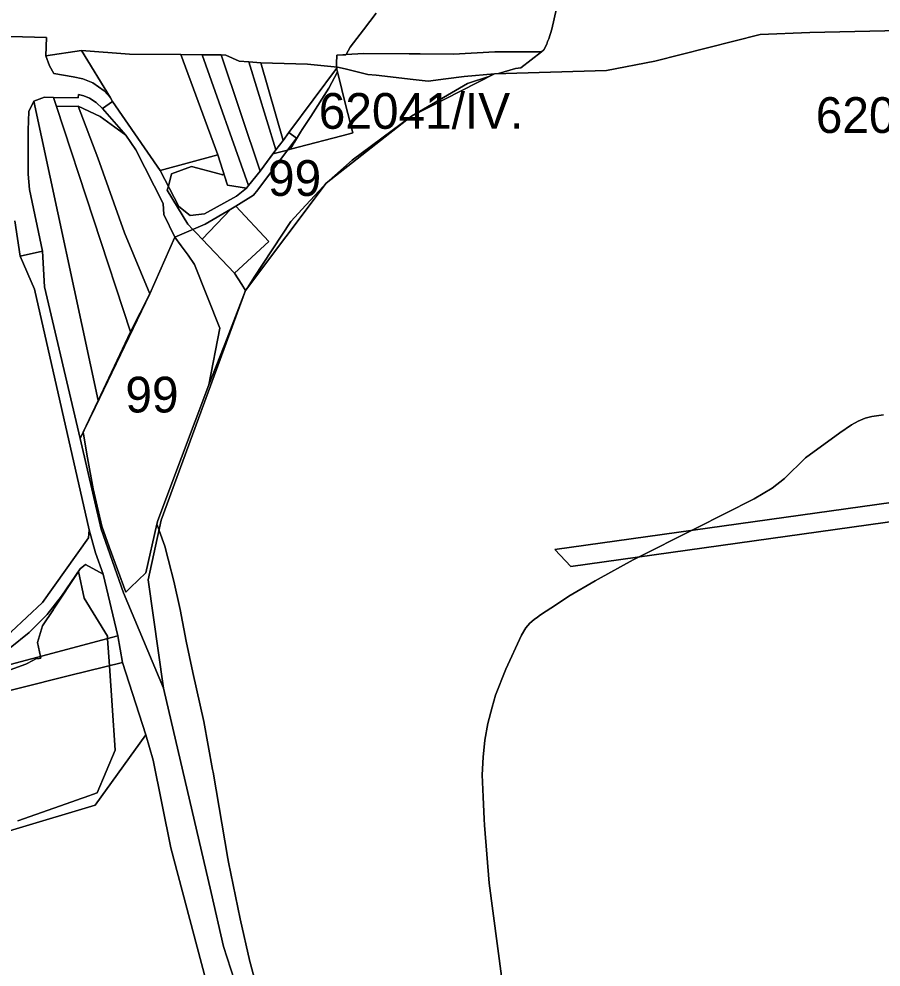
# Model space of a CAD drawing. Extents: x -521939 to -516426, y -1197857 to -1189551.
# Drawn here: x -519093.3 to -518731.6, y -1193402.1 to -1193004.4 of the extents above; entities that cross this region are included whole.
import ezdxf

# ---------------------------------------------------------------- set-up
doc = ezdxf.new("R2010")
doc.units = 0
for name, color, linetype in [('95560013', 7, 'Continuous'), ('95600013', 7, 'Continuous'), ('95610013', 7, 'Continuous'), ('95620013', 7, 'Continuous'), ('95640013', 7, 'Continuous'), ('95660013', 7, 'Continuous')]:
    doc.layers.add(name, color=color, linetype=linetype)

msp = doc.modelspace()

# ---------------------------------------------------------------- linework, layer by layer
at = {"layer": '95560013'}
msp.add_lwpolyline([(-519009.88, -1193061.29), (-519025.46, -1193019.32), (-519016.37, -1193019.41), (-518997.03, -1193074.16), (-518997.79, -1193075.34), (-519005.77, -1193074.1)], close=True, dxfattribs=at)
at = {"layer": '95600013'}
for points in [[(-519001.34, -1193412.48), (-519007.46, -1193393.47), (-519012.64, -1193370.77), (-519032.72, -1193285.1), (-519039.05, -1193239.66), (-519033.58, -1193214.67), (-518998.24, -1193118.29), (-518964.46, -1193073.28), (-518928.64, -1193045.14), (-518893.72, -1193027.32), (-518846.7, -1193025.98), (-518826.54, -1193022.13), (-518782.28, -1193010.93), (-518761.5, -1193009.97), (-518654.27, -1193007.7)], [(-518688.29, -1193201.76), (-518868.39, -1193226.97), (-518861.71, -1193234.11), (-518680.88, -1193208.8)]]:
    msp.add_lwpolyline(points, dxfattribs=at)
at = {"layer": '95610013'}
for points in [[(-519054.97, -1193037.51), (-519067.01, -1193017.55), (-519046.96, -1193019.18), (-519025.46, -1193019.32), (-519009.88, -1193061.29), (-519034.04, -1193067.86), (-519054.02, -1193039.03)], [(-518997.03, -1193074.16), (-519016.37, -1193019.41), (-519008.43, -1193019.45), (-518992.15, -1193068.17)], [(-518992.15, -1193068.17), (-519008.43, -1193019.45), (-519006.51, -1193019.53), (-519000.94, -1193022.11), (-518996.85, -1193022.41), (-518985.57, -1193059.25)], [(-518982.48, -1193055.34), (-518985.57, -1193059.25), (-518996.85, -1193022.41), (-518991.81, -1193022.8)], [(-518982.48, -1193055.34), (-518991.81, -1193022.8), (-518972.24, -1193023.25), (-518959.64, -1193024.58), (-518980, -1193052)], [(-519060.07, -1193164.39), (-519087.08, -1193038.9), (-519082.67, -1193037.22), (-519078.8, -1193037.27), (-519077.5, -1193041.07), (-519046.53, -1193135.65)], [(-519067.63, -1193180.4), (-519082.57, -1193116.69), (-519083.39, -1193101.82), (-519088.85, -1193075.94), (-519089.42, -1193069.44), (-519089.5, -1193051.02), (-519089.11, -1193043.23), (-519087.08, -1193038.9), (-519060.07, -1193164.39)], [(-519038.42, -1193119.66), (-519046.53, -1193135.65), (-519077.5, -1193041.07), (-519068.45, -1193040.92), (-519060.23, -1193062.58), (-519049.02, -1193094.14)], [(-519068.45, -1193040.92), (-519059.24, -1193045.26), (-519048.45, -1193053.16), (-519044.3, -1193059.21), (-519032.87, -1193081.73), (-519032.49, -1193086.43), (-519027.86, -1193095.83), (-519038.42, -1193119.66), (-519049.02, -1193094.14), (-519060.23, -1193062.58)]]:
    msp.add_lwpolyline(points, close=True, dxfattribs=at)
at = {"layer": '95620013'}
for points in [[(-519039.05, -1193239.66), (-519032.72, -1193285.1), (-519049.46, -1193245.15), (-519058.78, -1193218.39), (-519067.63, -1193180.4), (-519060.07, -1193164.39), (-519046.53, -1193135.65), (-519038.42, -1193119.66), (-519027.86, -1193095.83), (-519015.15, -1193090.46), (-519004.43, -1193084.1), (-519016.48, -1193096.79), (-519002.91, -1193111.04), (-518988.41, -1193097.77), (-519002.31, -1193082.85), (-518994.93, -1193078.21), (-518993.12, -1193076.06), (-518976.91, -1193054.31), (-518980, -1193052), (-518959.64, -1193024.58), (-518956.41, -1193025.34), (-518946.89, -1193027.59), (-518943.36, -1193028), (-518927.91, -1193029.78), (-518921.63, -1193030.5), (-518914.19, -1193029.54), (-518906.5, -1193028.54), (-518893.72, -1193027.32), (-518928.64, -1193045.14), (-518964.46, -1193073.28), (-518998.24, -1193118.29), (-519033.58, -1193214.67)], [(-519051.78, -1193263.19), (-519124.36, -1193282.37), (-519115.87, -1193279.15), (-519106.02, -1193274.02), (-519097.04, -1193268.18), (-519089.06, -1193261.77), (-519081.5, -1193254.17), (-519075.4, -1193246.52), (-519067.67, -1193235.07), (-519065.42, -1193233.19), (-519057.96, -1193237.27)], [(-519124.36, -1193282.37), (-519051.78, -1193263.19), (-519049.8, -1193274.26), (-519072.06, -1193279.85), (-519245.64, -1193323.44), (-519245.94, -1193321.3), (-519240.31, -1193313.01)], [(-519049.8, -1193274.26), (-519040.03, -1193304.65), (-519061.29, -1193334.23), (-519127.73, -1193353.98), (-519195.16, -1193370.61), (-519207.67, -1193377.01), (-519216.77, -1193386.17), (-519224.13, -1193393.57), (-519244.63, -1193400.06), (-519323.14, -1193420.3), (-519400.65, -1193437.87), (-519436.58, -1193400.77), (-519414.21, -1193393.4), (-519363, -1193379.33), (-519272.27, -1193354.6), (-519242.56, -1193344.82), (-519244.89, -1193329.7), (-519245.64, -1193323.44), (-519072.06, -1193279.85)]]:
    msp.add_lwpolyline(points, close=True, dxfattribs=at)
at = {"layer": '95640013'}
for points in [[(-518654.27, -1193007.7), (-518761.5, -1193009.97), (-518782.28, -1193010.93), (-518826.54, -1193022.13), (-518846.7, -1193025.98), (-518893.72, -1193027.32), (-518906.5, -1193028.54), (-518914.19, -1193029.54), (-518921.63, -1193030.5), (-518927.91, -1193029.78), (-518943.36, -1193028), (-518946.89, -1193027.59), (-518956.41, -1193025.34), (-518959.64, -1193024.58), (-518972.24, -1193023.25), (-518991.81, -1193022.8), (-518996.85, -1193022.41), (-519000.94, -1193022.11), (-519006.51, -1193019.53), (-519008.43, -1193019.45), (-519016.37, -1193019.41), (-519025.46, -1193019.32), (-519046.96, -1193019.18), (-519067.01, -1193017.55), (-519082.01, -1193019.86), (-519081.82, -1193012.11), (-519107.14, -1193011.48)], [(-519107.14, -1193011.48), (-519081.82, -1193012.11), (-519082.01, -1193019.86), (-519080.51, -1193024.08), (-519078.69, -1193027.26), (-519070.56, -1193028.61), (-519066.57, -1193029.49), (-519062.38, -1193031.14), (-519057.59, -1193034.55), (-519054.97, -1193037.51), (-519054.02, -1193039.03), (-519058.32, -1193041.95), (-519060.88, -1193039.35), (-519063.71, -1193037.53), (-519066.12, -1193036.54), (-519068.36, -1193036.01), (-519068.53, -1193037.41), (-519078.8, -1193037.27), (-519082.67, -1193037.22), (-519087.08, -1193038.9), (-519089.11, -1193043.23), (-519089.5, -1193051.02), (-519089.42, -1193069.44), (-519088.85, -1193075.94), (-519083.39, -1193101.82), (-519092.79, -1193103.81), (-519094.99, -1193089.06)], [(-519094.99, -1193089.06), (-519092.79, -1193103.81), (-519086.83, -1193117.76), (-519063.8, -1193218.73), (-519064.08, -1193221.98), (-519083.46, -1193249.19), (-519096.57, -1193261.51)], [(-519013.6, -1193412.23), (-519029.64, -1193352.06), (-519037.03, -1193315.32), (-519040.03, -1193304.65), (-519049.8, -1193274.26), (-519051.78, -1193263.19), (-519057.96, -1193237.27), (-519061.2, -1193228.34), (-519063.8, -1193218.73), (-519086.83, -1193117.76), (-519092.79, -1193103.81), (-519083.39, -1193101.82), (-519082.57, -1193116.69), (-519067.63, -1193180.4), (-519058.78, -1193218.39), (-519049.46, -1193245.15), (-519032.72, -1193285.1), (-519012.64, -1193370.77), (-519007.46, -1193393.47), (-519001.34, -1193412.48)]]:
    msp.add_lwpolyline(points, dxfattribs=at)
for points in [[(-519054.97, -1193037.51), (-519057.59, -1193034.55), (-519062.38, -1193031.14), (-519066.57, -1193029.49), (-519070.56, -1193028.61), (-519078.69, -1193027.26), (-519080.51, -1193024.08), (-519082.01, -1193019.86), (-519067.01, -1193017.55)], [(-519077.5, -1193041.07), (-519078.8, -1193037.27), (-519068.53, -1193037.41), (-519068.36, -1193036.01), (-519066.12, -1193036.54), (-519063.71, -1193037.53), (-519060.88, -1193039.35), (-519058.32, -1193041.95), (-519048.45, -1193053.16), (-519059.24, -1193045.26), (-519068.45, -1193040.92)], [(-519058.32, -1193041.95), (-519054.02, -1193039.03), (-519034.04, -1193067.86), (-519026.26, -1193082.98), (-519021.48, -1193086.74), (-519015.43, -1193086.04), (-519002.06, -1193078.67), (-518997.79, -1193075.34), (-518997.03, -1193074.16), (-518992.15, -1193068.17), (-518985.57, -1193059.25), (-518982.48, -1193055.34), (-518980, -1193052), (-518976.91, -1193054.31), (-518993.12, -1193076.06), (-518994.93, -1193078.21), (-519002.31, -1193082.85), (-519004.43, -1193084.1), (-519015.15, -1193090.46), (-519027.86, -1193095.83), (-519032.49, -1193086.43), (-519032.87, -1193081.73), (-519044.3, -1193059.21), (-519048.45, -1193053.16)], [(-519009.88, -1193061.29), (-519005.77, -1193074.1), (-518997.79, -1193075.34), (-519002.06, -1193078.67), (-519015.43, -1193086.04), (-519021.48, -1193086.74), (-519026.26, -1193082.98), (-519034.04, -1193067.86)], [(-519016.48, -1193096.79), (-519004.43, -1193084.1), (-519002.31, -1193082.85), (-518988.41, -1193097.77), (-519002.91, -1193111.04)], [(-518489.33, -1193173.91), (-518471.02, -1193171.35), (-518469.31, -1193179.19), (-518488.19, -1193181.83), (-518680.88, -1193208.8), (-518861.71, -1193234.11), (-518868.39, -1193226.97), (-518688.29, -1193201.76), (-518507.69, -1193176.48)], [(-519110.89, -1193271.43), (-519096.57, -1193261.51), (-519083.46, -1193249.19), (-519064.08, -1193221.98), (-519063.8, -1193218.73), (-519061.2, -1193228.34), (-519057.96, -1193237.27), (-519065.42, -1193233.19), (-519067.67, -1193235.07), (-519075.4, -1193246.52), (-519081.5, -1193254.17), (-519089.06, -1193261.77), (-519097.04, -1193268.18), (-519106.02, -1193274.02), (-519115.87, -1193279.15), (-519124.36, -1193282.37), (-519240.31, -1193313.01), (-519284.36, -1193324.57), (-519456.94, -1193369.86), (-519458.56, -1193374.41), (-519466.55, -1193363.58), (-519459.16, -1193366.31), (-519283.48, -1193320.18), (-519142.38, -1193283.13)], [(-519110.84, -1193580.01), (-519128.68, -1193547.96), (-519143.89, -1193520.55), (-519162.86, -1193486.08), (-519175.78, -1193463.01), (-519186.96, -1193442.78), (-519201.14, -1193416.51), (-519216.77, -1193386.17), (-519207.67, -1193377.01), (-519195.16, -1193370.61), (-519127.73, -1193353.98), (-519061.29, -1193334.23), (-519040.03, -1193304.65), (-519037.03, -1193315.32), (-519029.64, -1193352.06), (-519013.6, -1193412.23), (-518995.72, -1193458.59), (-518983.73, -1193485.98), (-518969.16, -1193519.14), (-518956.05, -1193564.77), (-518954.36, -1193589.13), (-519083.02, -1193619.12), (-519102.82, -1193594.23)]]:
    msp.add_lwpolyline(points, close=True, dxfattribs=at)
at = {"layer": '95660013'}
for points in [[(-518993.45, -1193410.66), (-518996.16, -1193400.77), (-518996.43, -1193399.77), (-519000.49, -1193381.92), (-519005.38, -1193358.13), (-519005.71, -1193356.53), (-519011.85, -1193320.37), (-519012.07, -1193319.15), (-519015.67, -1193299.04), (-519020.31, -1193278.53), (-519023.21, -1193265.43), (-519025.64, -1193252.1), (-519028.31, -1193240.16), (-519030.39, -1193232.05), (-519030.55, -1193231.45), (-519030.67, -1193231.03), (-519032.13, -1193225.55), (-519034.45, -1193218.95), (-519034.49, -1193218.84), (-519035.42, -1193216.35), (-519035.06, -1193214.75), (-519025.13, -1193188.35), (-519013.66, -1193157.84), (-519005.98, -1193138.27), (-518998.24, -1193118.29), (-518997.2, -1193116.7), (-518994.57, -1193112.69), (-518979.22, -1193089.31), (-518972.94, -1193082.49), (-518965.57, -1193074.48), (-518964.46, -1193073.28), (-518953.54, -1193063.59), (-518928.64, -1193045.14), (-518905.11, -1193031.36), (-518896.15, -1193028.56), (-518893.72, -1193027.32), (-518892.03, -1193027.27), (-518885.02, -1193025.08), (-518882.65, -1193024.86), (-518874.04, -1193018.1), (-518873.06, -1193017.33), (-518871.85, -1193014.87), (-518871.65, -1193014.34), (-518871.46, -1193013.83), (-518871.02, -1193012.64), (-518869.73, -1193008.59), (-518866.79, -1192995.54)], [(-518866.79, -1192995.54), (-518869.73, -1193008.59), (-518871.02, -1193012.64), (-518871.46, -1193013.83), (-518871.65, -1193014.34), (-518871.85, -1193014.87), (-518873.06, -1193017.33), (-518874.04, -1193018.1), (-518893.63, -1193018.2), (-518910.99, -1193019.08), (-518925.01, -1193018.97), (-518929.53, -1193018.93), (-518948.8, -1193018.78), (-518956.02, -1193019.33), (-518954.37, -1193016.12), (-518948.69, -1193008.93), (-518943.48, -1193001.98)], [(-518943.48, -1193001.98), (-518948.69, -1193008.93), (-518954.37, -1193016.12), (-518956.02, -1193019.33), (-518956.16, -1193019.34), (-518957.37, -1193019.42), (-518959.9, -1193019.6), (-518960.01, -1193023.02), (-518960.06, -1193024.54), (-518959.64, -1193024.58), (-518960.04, -1193025.12), (-518959.7, -1193026.47), (-518963.24, -1193033.33), (-518970.89, -1193045.33), (-518974.42, -1193050.66), (-518975.11, -1193051.81), (-518977.64, -1193056.05), (-518978.19, -1193056.98), (-518979.4, -1193059.01), (-518980.66, -1193059.34), (-518986.83, -1193060.96), (-518992.15, -1193068.17), (-518997.03, -1193074.16), (-518997.79, -1193075.34), (-519005.77, -1193074.1), (-519007.31, -1193069.29), (-519007.95, -1193069.75), (-519008.32, -1193069.65), (-519009.31, -1193069.37), (-519020.88, -1193066.18), (-519029.25, -1193069.37), (-519030.62, -1193074.5), (-519031.08, -1193076.2), (-519022.39, -1193090.46), (-519020.34, -1193092.65), (-519018.82, -1193094.28), (-519016.48, -1193096.79), (-519002.91, -1193111.04), (-518999.85, -1193115.79), (-518998.24, -1193118.29), (-519005.98, -1193138.27), (-519013.66, -1193157.84), (-519009.05, -1193134.14), (-519019.62, -1193107.34), (-519022.38, -1193103.49), (-519023.57, -1193101.82), (-519025.22, -1193099.51), (-519027.86, -1193095.83), (-519038.42, -1193119.66), (-519061.35, -1193167.3), (-519065.97, -1193176.91), (-519066.41, -1193177.81), (-519066.28, -1193178.52), (-519064.51, -1193188.41), (-519062.16, -1193201.53), (-519060.92, -1193206.91), (-519058.59, -1193217.08), (-519055.41, -1193225.8), (-519048.48, -1193244.78), (-519046.46, -1193242.85), (-519040.06, -1193236.72), (-519035.42, -1193216.35), (-519034.49, -1193218.84), (-519034.45, -1193218.95), (-519032.13, -1193225.55), (-519030.67, -1193231.03), (-519030.55, -1193231.45), (-519030.39, -1193232.05), (-519028.31, -1193240.16), (-519025.64, -1193252.1), (-519023.21, -1193265.43), (-519020.31, -1193278.53), (-519015.67, -1193299.04), (-519012.07, -1193319.15), (-519011.85, -1193320.37), (-519005.71, -1193356.53), (-519005.38, -1193358.13), (-519000.49, -1193381.92), (-518996.43, -1193399.77), (-518996.16, -1193400.77), (-518993.45, -1193410.66)], [(-518730.5, -1193170.49), (-518735.4, -1193171.07), (-518738.19, -1193171.77), (-518741.11, -1193173.06), (-518743.91, -1193174.57), (-518748.81, -1193177.95), (-518763.27, -1193188.45), (-518772.02, -1193197.08), (-518777.27, -1193201.17), (-518784.85, -1193205.6), (-518809.11, -1193217.96), (-518811.08, -1193218.95), (-518833.37, -1193230.14), (-518835.59, -1193231.26), (-518850.29, -1193239.31), (-518851.48, -1193240.01), (-518862.53, -1193246.54), (-518867.76, -1193249.95), (-518874.49, -1193254.35), (-518875.77, -1193255.31), (-518877.05, -1193256.28), (-518878.92, -1193257.85), (-518880.61, -1193259.84), (-518882.48, -1193262.81), (-518889.01, -1193277.1), (-518893.38, -1193288.06), (-518894.78, -1193293.08), (-518896.53, -1193299.96), (-518897.82, -1193306.96), (-518898.52, -1193314.07), (-518898.87, -1193321.42), (-518898.45, -1193330.74), (-518898.04, -1193340.06), (-518897.93, -1193342.53), (-518896.07, -1193366.91), (-518890.82, -1193405.87)], [(-518890.82, -1193405.87), (-518896.07, -1193366.91), (-518897.93, -1193342.53), (-518898.04, -1193340.06), (-518898.45, -1193330.74), (-518898.87, -1193321.42), (-518898.52, -1193314.07), (-518897.82, -1193306.96), (-518896.53, -1193299.96), (-518894.78, -1193293.08), (-518893.38, -1193288.06), (-518889.01, -1193277.1), (-518882.48, -1193262.81), (-518880.61, -1193259.84), (-518878.92, -1193257.85), (-518877.05, -1193256.28), (-518875.77, -1193255.31), (-518874.49, -1193254.35), (-518867.76, -1193249.95), (-518862.53, -1193246.54), (-518851.48, -1193240.01), (-518850.29, -1193239.31), (-518835.59, -1193231.26), (-518833.37, -1193230.14), (-518811.08, -1193218.95), (-518809.11, -1193217.96), (-518784.85, -1193205.6), (-518777.27, -1193201.17), (-518772.02, -1193197.08), (-518763.27, -1193188.45), (-518748.81, -1193177.95), (-518743.91, -1193174.57), (-518741.11, -1193173.06), (-518738.19, -1193171.77), (-518735.4, -1193171.07), (-518730.5, -1193170.49)], [(-519106.86, -1193280.88), (-519090.5, -1193275.02), (-519087.18, -1193273.31), (-519086.24, -1193272.83), (-519084.88, -1193272.59), (-519084.1, -1193272.46), (-519084.12, -1193272.36), (-519084.25, -1193271.77), (-519085.58, -1193265.98), (-519083.44, -1193258.98), (-519078.89, -1193252.09), (-519078.49, -1193251.48), (-519068.37, -1193236.16), (-519066.01, -1193247.29), (-519056.21, -1193263.27), (-519056.14, -1193264.34), (-519055.38, -1193275.66), (-519054.26, -1193292.35), (-519053.01, -1193311.08), (-519060.43, -1193328.98), (-519060.46, -1193329.05), (-519066.01, -1193330.99), (-519067.25, -1193331.42), (-519071.1, -1193332.76), (-519093.85, -1193340.71)], [(-519093.85, -1193340.71), (-519071.1, -1193332.76), (-519067.25, -1193331.42), (-519066.01, -1193330.99), (-519060.46, -1193329.05), (-519060.43, -1193328.98), (-519053.01, -1193311.08), (-519054.26, -1193292.35), (-519055.38, -1193275.66), (-519056.14, -1193264.34), (-519056.21, -1193263.27), (-519066.01, -1193247.29), (-519068.37, -1193236.16), (-519078.49, -1193251.48), (-519078.89, -1193252.09), (-519083.44, -1193258.98), (-519085.58, -1193265.98), (-519084.25, -1193271.77), (-519084.12, -1193272.36), (-519084.1, -1193272.46), (-519084.88, -1193272.59), (-519086.24, -1193272.83), (-519087.18, -1193273.31), (-519090.5, -1193275.02), (-519106.86, -1193280.88)]]:
    msp.add_lwpolyline(points, dxfattribs=at)
for points in [[(-518998.24, -1193118.29), (-518999.85, -1193115.79), (-519002.91, -1193111.04), (-519016.48, -1193096.79), (-519018.82, -1193094.28), (-519020.34, -1193092.65), (-519022.39, -1193090.46), (-519031.08, -1193076.2), (-519030.62, -1193074.5), (-519029.25, -1193069.37), (-519020.88, -1193066.18), (-519009.31, -1193069.37), (-519008.32, -1193069.65), (-519007.95, -1193069.75), (-519007.31, -1193069.29), (-519005.77, -1193074.1), (-518997.79, -1193075.34), (-518997.03, -1193074.16), (-518992.15, -1193068.17), (-518986.83, -1193060.96), (-518980.66, -1193059.34), (-518979.4, -1193059.01), (-518954.56, -1193052.49), (-518953.24, -1193052.17), (-518955.28, -1193044.06), (-518955.96, -1193041.34), (-518959.7, -1193026.47), (-518960.04, -1193025.12), (-518959.64, -1193024.58), (-518960.06, -1193024.54), (-518960.01, -1193023.02), (-518959.9, -1193019.6), (-518957.37, -1193019.42), (-518956.16, -1193019.34), (-518956.02, -1193019.33), (-518948.8, -1193018.78), (-518929.53, -1193018.93), (-518925.01, -1193018.97), (-518910.99, -1193019.08), (-518893.63, -1193018.2), (-518874.04, -1193018.1), (-518882.65, -1193024.86), (-518885.02, -1193025.08), (-518892.03, -1193027.27), (-518893.72, -1193027.32), (-518896.15, -1193028.56), (-518905.11, -1193031.36), (-518928.64, -1193045.14), (-518953.54, -1193063.59), (-518964.46, -1193073.28), (-518965.57, -1193074.48), (-518972.94, -1193082.49), (-518979.22, -1193089.31), (-518994.57, -1193112.69), (-518997.2, -1193116.7)], [(-518954.56, -1193052.49), (-518979.4, -1193059.01), (-518978.19, -1193056.98), (-518977.64, -1193056.05), (-518975.11, -1193051.81), (-518974.42, -1193050.66), (-518970.89, -1193045.33), (-518963.24, -1193033.33), (-518959.7, -1193026.47), (-518955.96, -1193041.34), (-518955.28, -1193044.06), (-518953.24, -1193052.17)], [(-519046.46, -1193242.85), (-519048.48, -1193244.78), (-519055.41, -1193225.8), (-519058.59, -1193217.08), (-519060.92, -1193206.91), (-519062.16, -1193201.53), (-519064.51, -1193188.41), (-519066.28, -1193178.52), (-519066.41, -1193177.81), (-519065.97, -1193176.91), (-519061.35, -1193167.3), (-519038.42, -1193119.66), (-519027.86, -1193095.83), (-519025.22, -1193099.51), (-519023.57, -1193101.82), (-519022.38, -1193103.49), (-519019.62, -1193107.34), (-519009.05, -1193134.14), (-519013.66, -1193157.84), (-519025.13, -1193188.35), (-519035.06, -1193214.75), (-519035.42, -1193216.35), (-519040.06, -1193236.72)]]:
    msp.add_lwpolyline(points, close=True, dxfattribs=at)

# ---------------------------------------------------------------- texts
for s, rotation, p in [('62041/IV.', 360, (-518967.51, -1193050.44)), ('62001/III.', 360, (-518758.94, -1193052.17)), ('99', 360, (-518988.82, -1193078.59)), ('99', 0, (-519048.65, -1193169.44))]:
    msp.add_text(s, height=15, rotation=rotation, dxfattribs=at).set_placement(p)

doc.saveas('drawing.dxf')
